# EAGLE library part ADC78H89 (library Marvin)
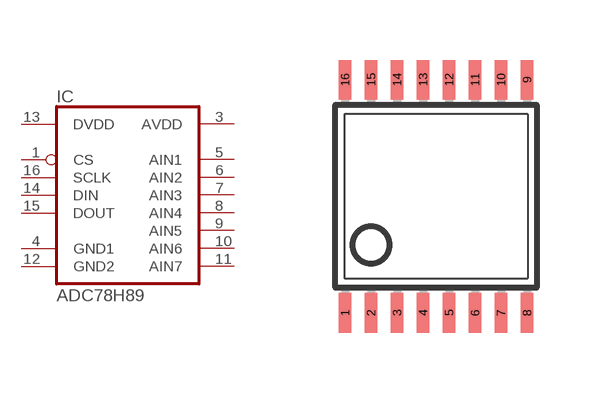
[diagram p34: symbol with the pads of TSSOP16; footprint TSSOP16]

Designator prefix IC

## ADC78H89  [TSSOP16]
1  CS
3  AVDD
4  GND1
5  AIN1
6  AIN2
7  AIN3
8  AIN4
9  AIN5
10  AIN6
11  AIN7
12  GND2
13  DVDD
14  DIN
15  DOUT
16  SCLK

## Footprint TSSOP16 (pad centres in mm)
smd 0.305 x 0.991: 1 -2.275,-2.918; 2 -1.625,-2.918; 3 -0.975,-2.918; 4 -0.325,-2.918; 5 0.325,-2.918; 6 0.975,-2.918; 7 1.625,-2.918; 8 2.275,-2.918; 9 2.275,2.918; 10 1.625,2.918; 11 0.975,2.918; 12 0.325,2.918; 13 -0.325,2.918; 14 -0.975,2.918; 15 -1.625,2.918; 16 -2.275,2.918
